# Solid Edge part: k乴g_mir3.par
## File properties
Last saved by: Anon
Revision: 53
Accuracy: 0,990
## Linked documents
lg.par
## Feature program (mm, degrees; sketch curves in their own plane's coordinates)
part copy "CopiedPart_1"
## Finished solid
Body 1: solid body, 36 faces, 71 edges, 39 vertices.
  Faces by surface: cylinder 15, plane 14, torus 6, spline 1
  Edges by curve: circle 35, line 25, intersection 11
Bounding box of the edges (mm; curved faces can reach further): 13.750 x 17.466 x 24.148, from (-11.5, -8.3909, -15) to (2.25, 9.0752, 9.1476).
Cylindrical faces by radius (mm): R0.5 x3, R1 x7, R1.5 x3, R2.25 x2
Toroidal faces (ring radius, tube radius in mm): R0.5 r1 x2, R1 r0.5 x2, R2 r1 x2
Planar faces by outward normal: +x 3, +y 2, +z 3, -x 1, -y 2, -z 1, oblique 2
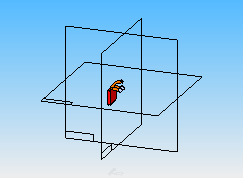
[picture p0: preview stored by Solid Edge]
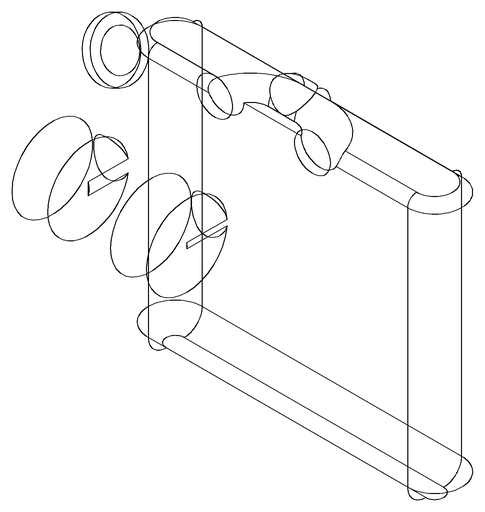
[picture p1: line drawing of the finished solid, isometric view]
